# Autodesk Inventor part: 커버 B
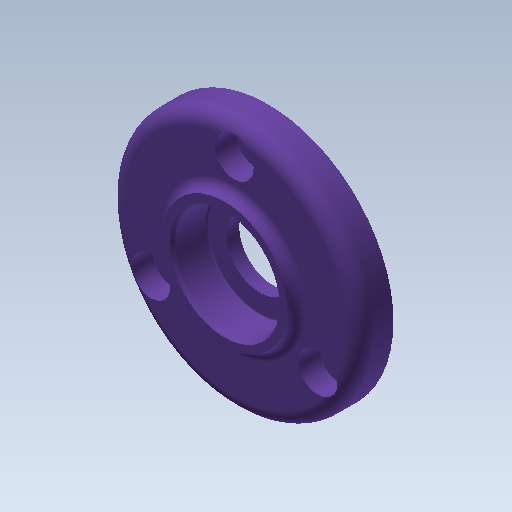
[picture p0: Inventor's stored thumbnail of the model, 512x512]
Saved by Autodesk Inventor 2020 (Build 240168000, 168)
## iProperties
Created: 2020-04
Part Number: 커버 B
Material: 알루미늄 6061
Document SubType Name: Modeling
Designer: mduedu
Density: 2.71 g/cm^3
Mass: 35.0669 g
Surface Area: 63.5386 cm^2
Volume: 12.9398 cm^3
Appearance: 보라색
Author: mduedu
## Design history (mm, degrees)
sketch "스케치1"
  geometry: C1 r 26 at (0, 0); 1 further point
  constraints: 1 centre point, 1 coincident
  dimensions: "d0" = 52 diameter of C1
extrude "돌출1" new body sketch "스케치1" distance "d1" = 7; taper "d2" = 0 deg
sketch "스케치6"
  geometry: C1 r 13 at (0, 0); 1 further point
  constraints: 1 centre point, 1 coincident
  dimensions: "d29" = 26 diameter of C1
extrude "돌출5" join sketch "스케치6" distance "d30" = 2; taper "d31" = 0 deg
fillet "모깎기2" dims "d7" = 3
fillet "모깎기4" dims "d33" = 2
sketch "스케치3" dims "d8" = 40
  geometry: 3 further points
  constraints: 2 vertical alignment, 1 coincident, 2 other
hole "구멍1" sketch "스케치3" at (0, 20) diameter "d9" = 4.5; stored, may be unused: countersink angle "d13" = 90 deg, drill point angle "d15" = 118 deg; dims "d10" = 6, "d11" = 8, "d12" = 4.4, "d14" = 8
sketch "스케치4"
  geometry: C1 r 14 at (0, 0); 1 further point
  constraints: 1 centre point, 1 coincident
  dimensions: "d19" = 28 diameter of C1
extrude "돌출3" join sketch "스케치4" distance "d20" = 4; taper "d21" = 0 deg
sketch "스케치5"
  geometry: C1 r 12 at (0, 0); 1 further point
  constraints: 1 centre point, 1 coincident
  dimensions: "d22" = 24 diameter of C1
extrude "돌출4" cut sketch "스케치5" distance "d23" = 3; taper "d24" = 0 deg
fillet "모깎기3" dims "d25" = 3
chamfer "모따기1" distance "d26" = 0.5; stored, may be unused: second distance "d27" = 2, angle "d28" = 45 deg
sketch "스케치7"
  geometry: 2 further points
  constraints: 1 coincident
hole "구멍2" sketch "스케치7" at (0, 0) diameter "d34" = 14; stored, may be unused: countersink angle "d38" = 90 deg, drill point angle "d40" = 118 deg; dims "d35" = 6, "d36" = 22, "d37" = 7.3, "d39" = 8
fillet "모깎기5" dims "d41" = 0.3
chamfer "모따기2" distance "d42" = 0.7; stored, may be unused: second distance "d43" = 2, angle "d44" = 30 deg
node "솔리드1"
pattern_circular "원형 패턴1" dims angle "d17" = 360 deg
